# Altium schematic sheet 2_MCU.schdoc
size 431 x 309 mm; Symbol: Sheet-Symbol_A3; Device: Sheet-Symbol_A3; Company: 嘉立创EDA; Version: V1.0; Page Size: A3; @Project Name: 辉光管_2024.2.16; @Page Count: 3; @Update Date: 2024-07-19; @Create Date: 2024-02-16; @Schematic Name: Schematic1; @Page No: 2; @Page Name: MCU
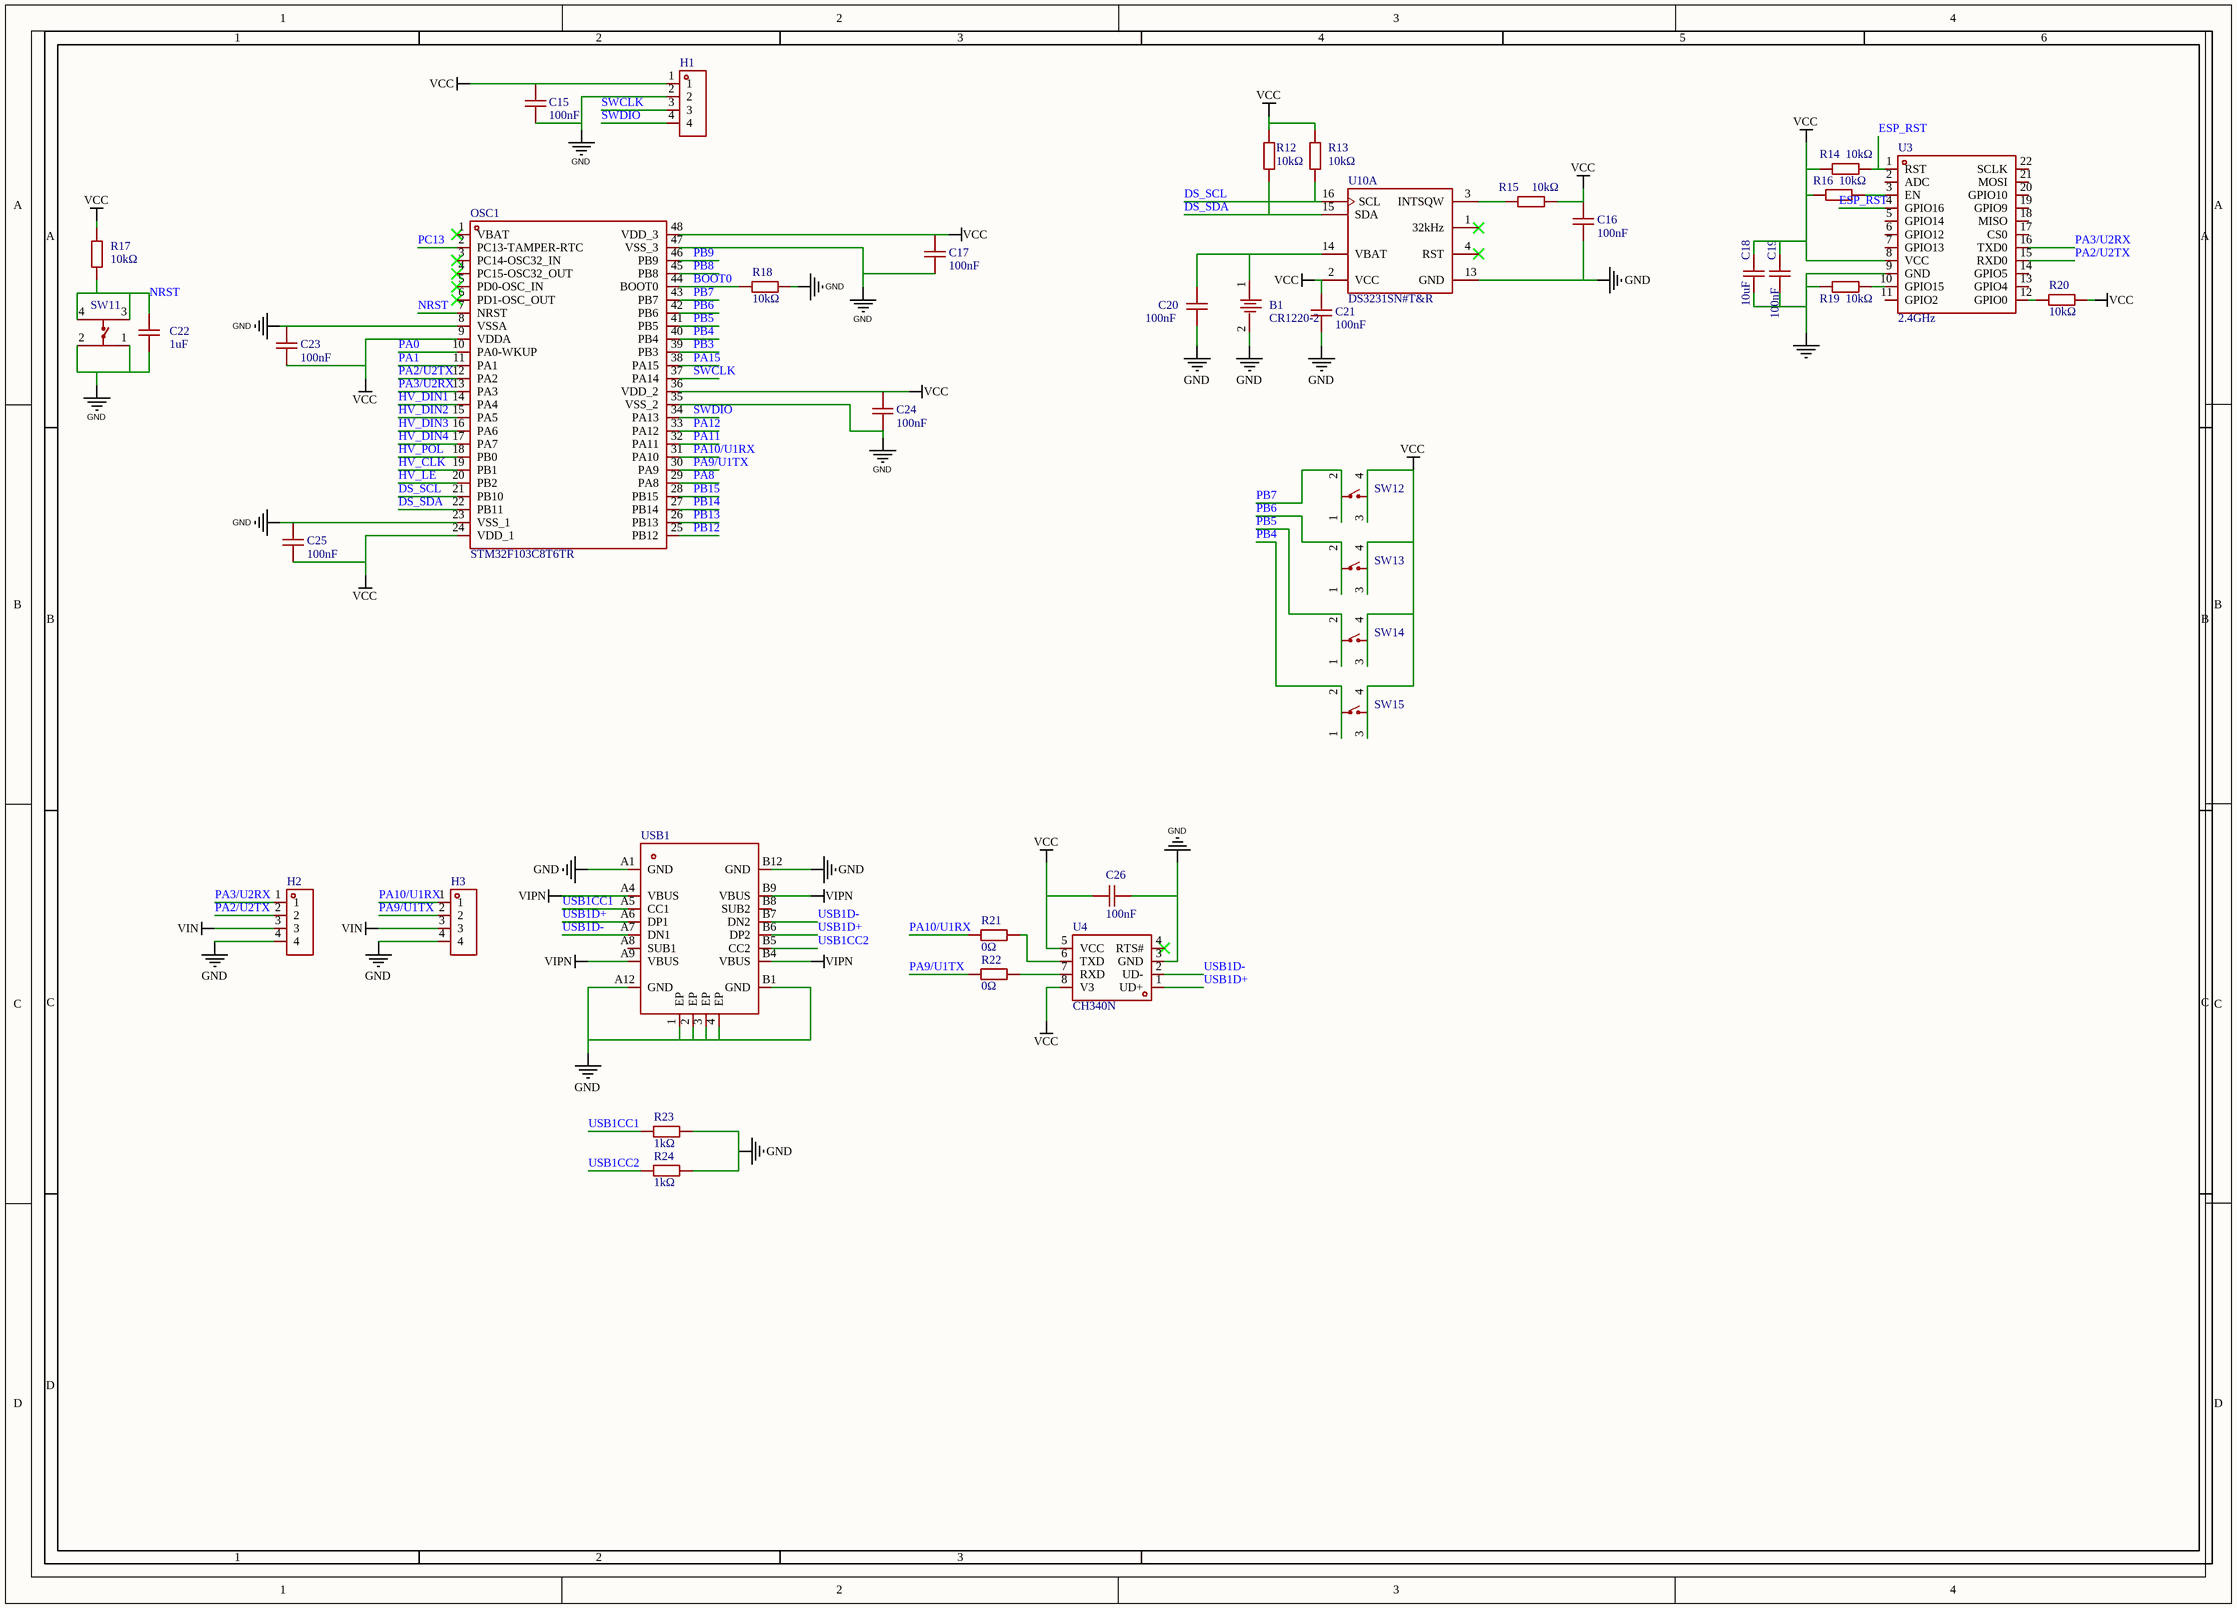
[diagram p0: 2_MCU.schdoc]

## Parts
B1  CR1220-2  [BAT-SMD_CR1220-2]  (value not drawn)
C15  100nF  [C0603]  (value not drawn)
C16  100nF  [C0603]  (value not drawn)
C17  100nF  [C0603]  (value not drawn)
C18  10uF  [C0805]  (value not drawn)
C19  100nF  [C0603]  (value not drawn)
C20  100nF  [C0603]  (value not drawn)
C21  100nF  [C0603]  (value not drawn)
C22  1uF  [C0603]  (value not drawn)
C23  100nF  [C0603]  (value not drawn)
C24  100nF  [C0603]  (value not drawn)
C25  100nF  [C0603]  (value not drawn)
C26  100nF  [C0603]  (value not drawn)
H1  PZ254V-11-04P  [HDR-TH_4P-P2.54-V-M]  (value not drawn)
H2  PZ254V-11-04P  [HDR-TH_4P-P2.54-V-M]  (value not drawn)
H3  PZ254V-11-04P  [HDR-TH_4P-P2.54-V-M]  (value not drawn)
OSC1  STM32F103C8T6TR  [LQFP-48_L7.0-W7.0-P0.50-LS9.0-BL]  (value not drawn)
R12  10kΩ  [R0603]  (value not drawn)
R13  10kΩ  [R0603]  (value not drawn)
R14  10kΩ  [R0603]  (value not drawn)
R15  10kΩ  [R0603]  (value not drawn)
R16  10kΩ  [R0603]  (value not drawn)
R17  10kΩ  [R0603]  (value not drawn)
R18  10kΩ  [R0603]  (value not drawn)
R19  10kΩ  [R0603]  (value not drawn)
R20  10kΩ  [R0603]  (value not drawn)
R21  0Ω  [R0603]  (value not drawn)
R22  0Ω  [R0603]  (value not drawn)
R23  1kΩ  [R0603]  (value not drawn)
R24  1kΩ  [R0603]  (value not drawn)
SW11  TS-1102S-B-A-B  [SW-SMD_4P-L6.0-W6.0-P4.50-LS8.6]  (value not drawn)
SW12  KH-6X6X5H-STM  [SW-SMD_4P-L6.0-W6.0-P4.50-LS9.0-2]  (value not drawn)
SW13  KH-6X6X5H-STM  [SW-SMD_4P-L6.0-W6.0-P4.50-LS9.0-2]  (value not drawn)
SW14  KH-6X6X5H-STM  [SW-SMD_4P-L6.0-W6.0-P4.50-LS9.0-2]  (value not drawn)
SW15  KH-6X6X5H-STM  [SW-SMD_4P-L6.0-W6.0-P4.50-LS9.0-2]  (value not drawn)
U3  2.4GHz  [WIFIM-SMD_ESP-12F-ESP8266MOD]  (value not drawn)
U4  CH340N  [SOP-8_L4.9-W3.9-P1.27-LS6.0-BL]  (value not drawn)
U10  DS3231SN#T&R  [SOIC-16_L10.3-W7.5-P1.27-LS10.3-BL]  (value not drawn)  (part A of 2)
USB1  KH-TYPE-C-16P  [USB-C-SMD_KH-TYPE-C-16P]  (value not drawn)

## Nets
GND: B1.2 C15.1 C16.1 C17.1 C18.1 C19.2 C20.1 C21.1 C22.1 C23.2 C24.1 C25.2 C26.1 H1.2 H2.4 H3.4 OSC1.8(VSSA) OSC1.23(VSS_1) OSC1.35(VSS_2) OSC1.47(VSS_3) R18.1 R19.2 R23.2 R24.2 SW11.1 SW11.2 U3.9(GND) U4.3(GND) U10.13(GND) USB1.1(EP) USB1.2(EP) USB1.3(EP) USB1.4(EP) USB1.A1(GND) USB1.A12(GND) USB1.B1(GND) USB1.B12(GND)
VCC: C15.2 C16.2 C17.2 C18.2 C19.1 C21.2 C23.1 C24.2 C25.1 C26.2 H1.1 OSC1.9(VDDA) OSC1.24(VDD_1) OSC1.36(VDD_2) OSC1.48(VDD_3) R12.2 R13.2 R14.2 R15.1 R16.2 R17.1 R20.1 SW12.3 SW12.4 SW13.3 SW13.4 SW14.3 SW14.4 SW15.3 SW15.4 U3.8(VCC) U4.5(VCC) U4.8(V3) U10.2(VCC)
VIN: H2.3 H3.3
VIPN: USB1.A4(VBUS) USB1.A9(VBUS) USB1.B4(VBUS) USB1.B9(VBUS)
BOOT0: OSC1.44(BOOT0) R18.2
DS_SCL: OSC1.21(PB10) R13.1 U10.16(SCL)
DS_SDA: OSC1.22(PB11) R12.1 U10.15(SDA)
ESP_RST: R14.1 U3.1(RST) U3.4(GPIO16)
HV_CLK: OSC1.19(PB1)
HV_DIN1: OSC1.14(PA4)
HV_DIN2: OSC1.15(PA5)
HV_DIN3: OSC1.16(PA6)
HV_DIN4: OSC1.17(PA7)
HV_LE: OSC1.20(PB2)
HV_POL: OSC1.18(PB0)
NRST: C22.2 OSC1.7(NRST) R17.2 SW11.3 SW11.4
PA0: OSC1.10(PA0-WKUP)
PA1: OSC1.11(PA1)
PA2/U2TX: H2.2 OSC1.12(PA2) U3.15(RXD0)
PA3/U2RX: H2.1 OSC1.13(PA3) U3.16(TXD0)
PA8: OSC1.29(PA8)
PA9/U1TX: H3.2 OSC1.30(PA9) R22.2
PA10/U1RX: H3.1 OSC1.31(PA10) R21.2
PA11: OSC1.32(PA11)
PA12: OSC1.33(PA12)
PA15: OSC1.38(PA15)
PB3: OSC1.39(PB3)
PB4: OSC1.40(PB4) SW15.1 SW15.2
PB5: OSC1.41(PB5) SW14.1 SW14.2
PB6: OSC1.42(PB6) SW13.1 SW13.2
PB7: OSC1.43(PB7) SW12.1 SW12.2
PB8: OSC1.45(PB8)
PB9: OSC1.46(PB9)
PB12: OSC1.25(PB12)
PB13: OSC1.26(PB13)
PB14: OSC1.27(PB14)
PB15: OSC1.28(PB15)
PC13: OSC1.2(PC13-TAMPER-RTC)
SWCLK: H1.3 OSC1.37(PA14)
SWDIO: H1.4 OSC1.34(PA13)
USB1CC1: R23.1 USB1.A5(CC1)
USB1CC2: R24.1 USB1.B5(CC2)
USB1D+: U4.1(UD+) USB1.A6(DP1) USB1.B6(DP2)
USB1D-: U4.2(UD-) USB1.A7(DN1) USB1.B7(DN2)
NetB1_1: B1.1 C20.2 U10.14(VBAT)
NetR15_2: R15.2 U10.3(INTSQW)
NetR16_1: R16.1 U3.3(EN)
NetR19_1: R19.1 U3.10(GPIO15)
NetR20_2: R20.2 U3.12(GPIO0)
NetR21_1: R21.1 U4.6(TXD)
NetR22_1: R22.1 U4.7(RXD)

Not connected (* = marked no-connect by the designer): OSC1 1(VBAT)* 3(PC14-OSC32_IN)* 4(PC15-OSC32_OUT)* 5(PD0-OSC_IN)* 6(PD1-OSC_OUT)*; U3 2(ADC) 5(GPIO14) 6(GPIO12) 7(GPIO13) 11(GPIO2) 13(GPIO4) 14(GPIO5) 17(CS0) 18(MISO) 19(GPIO9) 20(GPIO10) 21(MOSI) 22(SCLK); U4 4(RTS#)*; U10 1(32kHz)* 4(RST)*; USB1 A8(SUB1) B8(SUB2)

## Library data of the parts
B1 = CR1220-2: 连接器类型:电池底座;适用电池规格:CR1220;工作温度范围:-;; Manufacturer: Q&J; Add into BOM: yes; Connector Type: 电池底座; Battery Type: CR1220
C15-C17 C19-C21 C23-C26 = 0603B104K500NT: 容值:100nF;精度:±10%;额定电压:50V;材质(温度系数):X7R;; Manufacturer: FH(风华); Add into BOM: yes; Tolerance: ±10%; Voltage Rated: 50V; Temperature Coefficient: X7R
C18 = 0805X106K250NT: 容值:10uF;精度:±10%;额定电压:25V;材质(温度系数):X5R;; Manufacturer: FH(风华); Add into BOM: yes; Tolerance: ±10%; Voltage Rated: 25V; Temperature Coefficient: X5R
C22 = 0603B105K250NT: 容值:1uF;精度:±10%;额定电压:25V;材质(温度系数):X7R;; Manufacturer: FH(风华); Add into BOM: yes; Tolerance: ±10%; Voltage Rated: 25V; Temperature Coefficient: X7R
H1-H3 = PZ254V-11-04P: 插针结构:1x4P;间距:2.54mm;行距:-;圆针/方针:方针;安装类型:直插;排数:单排;总PIN位数:4P;额定电流:3A;额定电压:250V;配合针长度:6mm;塑高:2.5mm;端接针长度:3mm;触头材质:-;工作温度范围:-40℃~+105℃;颜色:黑色;; Manufacturer: XFCN(兴飞); Symbol: PZ254V-11-04P_C2691448; Add into BOM: yes; Pin Structure: 1x4P; Pitch: 2.54mm; Circluar Pins/Square Pins: 方针; Current Rating (Max): 3A; Voltage Rating (Max): 250V
OSC1 = STM32F103C8T6TR: CPU内核:CM3;程序存储容量:64KB;RAM总容量:20KB;GPIO端口数量:37;工作电压范围:2V~3.6V;CPU最大主频:72MHz;程序存储器类型:-;; Manufacturer: ST(意法半导体); Add into BOM: yes; CPU Core: CM3; Program Storage Size: 64KB; RAM Size: 20KB; GPIO Ports Number: 37; CPU Maximum Speed: 72MHz; ADC (Bit): 12bit; Universal Serial Bus: 有; Peripheral/Function: 温度传感器
R12-R20 = 0603WAF1002T5E: 电阻类型:厚膜电阻;阻值:10kΩ;精度:±1%;功率:100mW;; Manufacturer: UNI-ROYAL(厚声); Add into BOM: yes; Tolerance: ±1%; Power(Watts): 100mW; Temperature Coefficient: ±100ppm/℃; Overload Voltage (Max): 75V
R21 R22 = 0603WAF0000T5E: 电阻类型:厚膜电阻;阻值:0Ω;精度:±1%;功率:100mW;; Manufacturer: UNI-ROYAL(厚声); Add into BOM: yes; Tolerance: ±1%; Power(Watts): 100mW; Overload Voltage (Max): 75V
R23 R24 = RC0603FR-071KL: 电阻类型:厚膜电阻;阻值:1kΩ;精度:±1%;功率:100mW;最大工作电压:75V;温度系数:±100ppm/℃;; Manufacturer: YAGEO(国巨); Add into BOM: yes; Tolerance: ±1%; Power(Watts): 100mW; Overload Voltage (Max): 75V
SW11 = TS-1102S-B-A-B: 电路结构:单刀单掷;按钮形状:圆形按钮;作用力:160gf;安装方式:立贴;开关长度:6mm;开关宽度:6mm;开关高度:4.3mm;带支架:不带;触点电流:50mA;额定电压(DC):12V;绝缘电阻:-;带灯:无;机械寿命:30万次;; Manufacturer: XKB Connectivity(中国星坤); Add into BOM: yes; Circuit: 单刀单掷; Actuator Style: 圆形按钮; Operating Force: 160gf; Switch Length: 6mm; Switch Height: 4.3mm; Strike Gundam: 不带; Contact Current: 50mA; Voltage Rating (DC): 12V; Actuator/Cap Color: 黑色; With Lamp: 无; Mechanical Life: 30万次
SW12-SW15 = KH-6X6X5H-STM: 电路结构:单刀单掷;按钮形状:圆形按钮;安装方式:立贴;开关长度:6mm;开关宽度:6mm;开关高度:5mm;带支架:不带;触点电流:50mA;额定电压(DC):12V;机械寿命:8万次;; Manufacturer: kinghelm(金航标); Add into BOM: yes; Circuit: 单刀单掷; Actuator Style: 圆形按钮; Switch Length: 6mm; Switch Height: 5mm; Strike Gundam: 不带; Contact Current: 50mA; Voltage Rating (DC): 12V; Actuator/Cap Color: 黑色; Pin Style: 鸥翼型; Mechanical Life: 8万次
U3 = ESP-12F(ESP8266MOD): 核心处理器:ESP8266芯片;频率:2.4GHz;天线形式:板载PCB天线;发射功率:16dBm;接收灵敏度:-90dBm;; Manufacturer: Ai-Thinker(安信可); Add into BOM: yes; Support Interface: GPIO；UART；I2C；PWM；SPI；ADC; Output Power: 16dBm; Operating Voltage: 3.3V; Receive  Current: 120mA; Send  Current: 170mA; Sensitivity: -90dBm
U4 = CH340N: Manufacturer: WCH(南京沁恒); Symbol: CH340N_C2977777; Add into BOM: yes
U10 = DS3231SN#T&R: 接口:I2C;; Manufacturer: ADI(亚德诺)/MAXIM(美信); Add into BOM: yes; Interface: I2C; Operating Voltage: 2.3V~5.5V
USB1 = KH-TYPE-C-16P: 连接器类型:Type-C;标准:-;公母:母;端口数量:1;触点数量:16P;安装方式:卧贴;额定电流 - 电源:3A;工作温度范围:-40℃~+85℃;; Manufacturer: kinghelm(金航标); Add into BOM: yes; Connector Type: Type-C; Gender: 母; Number of Ports: 1; Number of Contacts: 16P; Current Rating - Power (Max): 3A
